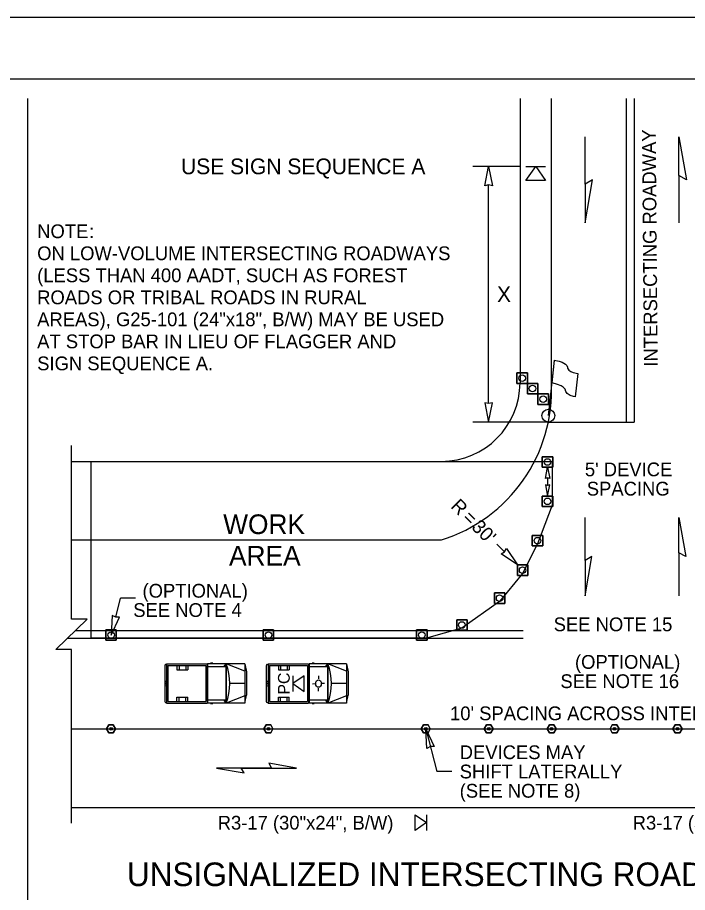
# Model space of a CAD drawing. Extents: x 99998.9 to 100095.7, y 99995 to 100010.7.
# Drawn here: x 100065.2 to 100068.607, y 100006.238 to 100010.687 of the extents above; entities that cross this region are included whole.
import ezdxf

# ---------------------------------------------------------------- set-up
doc = ezdxf.new("R2010")
doc.units = 0
for name, color, linetype in [('RD_ED_ShoulderPavedEdge', 7, 'Continuous'), ('RD_MK_LineDblYellowCenter', 7, 'Continuous'), ('RD_MK_LineEdgeWhite', 7, 'Continuous'), ('RD_MK_LineStop', 7, 'Continuous'), ('SH_DE_DetailBody1Text', 7, 'Continuous'), ('SH_DE_DetailHeading2Text', 7, 'Continuous'), ('SH_GI_PlotLimits', 7, 'Continuous'), ('SH_GI_SheetBorder', 7, 'Continuous'), ('TR_WZ_FlaggingStation', 7, 'Continuous'), ('TR_WZ_MotoristVehicle', 7, 'Continuous'), ('TR_WZ_PortableSignMountBlk-Org', 7, 'Continuous'), ('TR_WZ_PortableSignMountBlk-Wht', 7, 'Continuous'), ('TR_WZ_TrafficCone', 7, 'Continuous'), ('TR_WZ_TubularMarker', 7, 'Continuous'), ('TR_WZ_WorkAreaLabel', 7, 'Continuous'), ('TR_WZ_WorkZoneDetails', 7, 'Continuous'), ('TR_WZ_WorkZoneTextCurrent', 7, 'Continuous')]:
    doc.layers.add(name, color=color, linetype=linetype)

msp = doc.modelspace()

# ---------------------------------------------------------------- linework, layer by layer
at = {"layer": 'RD_ED_ShoulderPavedEdge'}
for p, q in [((100065.475, 100008.4304), (100067.355, 100008.4304)), ((100065.475, 100006.6704), (100070.275, 100006.6704))]:
    msp.add_line(p, q, dxfattribs=at)
msp.add_lwpolyline([(100067.755, 100010.275), (100067.755, 100008.8304)], dxfattribs=at)
msp.add_arc((100067.355, 100008.8304), 0.4, 270, 0, dxfattribs=at)
at = {"layer": 'RD_MK_LineDblYellowCenter'}
for p, q in [((100068.295, 100010.275), (100068.295, 100008.6304)), ((100068.335, 100010.275), (100068.335, 100008.6304)), ((100065.4957, 100007.5704), (100067.7712, 100007.5704)), ((100065.4543, 100007.5305), (100067.7712, 100007.5305))]:
    msp.add_line(p, q, dxfattribs=at)
at = {"layer": 'RD_MK_LineEdgeWhite'}
for p, q in [((100067.915, 100008.8304), (100067.915, 100010.275)), ((100065.475, 100008.0305), (100067.355, 100008.0305)), ((100065.475, 100007.0704), (100070.275, 100007.0704))]:
    msp.add_line(p, q, dxfattribs=at)
msp.add_arc((100067.1158, 100008.7939), 0.8, 287.3948, 2.6212, dxfattribs=at)
at = {"layer": 'RD_MK_LineStop'}
msp.add_line((100067.899, 100008.6304), (100068.335, 100008.6304), dxfattribs=at)
at = {"layer": 'SH_GI_PlotLimits'}
msp.add_lwpolyline([(100059.0625, 99999.6875), (100076.0625, 99999.6875), (100076.0625, 100010.6875), (100059.0625, 100010.6875)], close=True, dxfattribs=at)
at = {"layer": 'SH_GI_SheetBorder'}
msp.add_line((100060, 100010.375), (100075.75, 100010.375), dxfattribs=at)
at = {"layer": 'TR_WZ_FlaggingStation'}
for p, q in [((100067.899, 100008.6629), (100067.931, 100008.9439)), ((100067.918, 100008.8299), (100067.9311, 100008.9442)), ((100068.049, 100008.8764), (100068.0357, 100008.7592)), ((100067.918, 100008.8299), (100067.918, 100008.8299))]:
    msp.add_line(p, q, dxfattribs=at)
for points in [[(100067.9311, 100008.9442), (100067.9368, 100008.9429), (100067.9546, 100008.9395), (100067.9685, 100008.9353), (100067.9781, 100008.9292), (100067.9867, 100008.9245), (100067.9923, 100008.9177), (100067.9966, 100008.9098), (100067.9971, 100008.9037), (100068.0025, 100008.8944), (100068.0133, 100008.887), (100068.0257, 100008.8818), (100068.049, 100008.8764)], [(100068.0357, 100008.7592), (100068.0276, 100008.7606), (100068.0099, 100008.7653), (100067.9942, 100008.7758), (100067.9877, 100008.7863), (100067.9838, 100008.7966), (100067.9747, 100008.8075), (100067.9637, 100008.8137), (100067.9464, 100008.8208), (100067.918, 100008.8299)]]:
    msp.add_lwpolyline(points, dxfattribs=at)
msp.add_circle((100067.899, 100008.6629), 0.0325, dxfattribs=at)
at = {"layer": 'TR_WZ_MotoristVehicle'}
for p, q in [((100065.9487, 100007.3911), (100065.9487, 100007.2098)), ((100065.9532, 100007.3972), (100065.9577, 100007.3972)), ((100065.9577, 100007.3972), (100065.9577, 100007.2037)), ((100065.9584, 100007.4005), (100066.1641, 100007.4005)), ((100065.9584, 100007.4005), (100065.9584, 100007.2005)), ((100065.9642, 100007.3925), (100065.9642, 100007.2084)), ((100065.9642, 100007.3925), (100066.1582, 100007.3925)), ((100066.0106, 100007.3925), (100066.0106, 100007.3695)), ((100066.0106, 100007.3695), (100066.0655, 100007.3695)), ((100066.0215, 100007.3925), (100066.0215, 100007.3695)), ((100066.0556, 100007.3925), (100066.0556, 100007.3695)), ((100066.0655, 100007.3925), (100066.0655, 100007.3695)), ((100066.1582, 100007.3925), (100066.1582, 100007.2084)), ((100066.1641, 100007.4005), (100066.1641, 100007.2005)), ((100066.1668, 100007.4005), (100066.1668, 100007.2005)), ((100066.3557, 100007.4005), (100066.1668, 100007.4005)), ((100066.2596, 100007.385), (100066.1668, 100007.385)), ((100066.1926, 100007.4033), (100066.1813, 100007.4033)), ((100066.2596, 100007.4005), (100066.2475, 100007.385)), ((100066.2596, 100007.4005), (100066.2596, 100007.2005)), ((100066.2613, 100007.4005), (100066.2613, 100007.2005)), ((100066.3557, 100007.3638), (100066.2613, 100007.4005)), ((100066.3557, 100007.4005), (100066.3557, 100007.2005)), ((100066.3557, 100007.4005), (100066.365, 100007.3601)), ((100066.465, 100007.3911), (100066.465, 100007.2098)), ((100066.4695, 100007.3972), (100066.4739, 100007.3972)), ((100066.4739, 100007.3972), (100066.4739, 100007.2037)), ((100066.4746, 100007.4005), (100066.6803, 100007.4005)), ((100066.4746, 100007.4005), (100066.4746, 100007.2005)), ((100066.4805, 100007.3925), (100066.4805, 100007.2084)), ((100066.4805, 100007.3925), (100066.6745, 100007.3925)), ((100066.5268, 100007.3925), (100066.5268, 100007.3695)), ((100066.5268, 100007.3695), (100066.5818, 100007.3695)), ((100066.5378, 100007.3925), (100066.5378, 100007.3695)), ((100066.5718, 100007.3925), (100066.5718, 100007.3695)), ((100066.5818, 100007.3925), (100066.5818, 100007.3695)), ((100066.6745, 100007.3925), (100066.6745, 100007.2084)), ((100066.6803, 100007.4005), (100066.6803, 100007.2005)), ((100066.6831, 100007.4005), (100066.6831, 100007.2005)), ((100066.872, 100007.4005), (100066.6831, 100007.4005)), ((100066.7758, 100007.385), (100066.6831, 100007.385)), ((100066.7089, 100007.4033), (100066.6975, 100007.4033)), ((100066.7758, 100007.4005), (100066.7638, 100007.385)), ((100066.7758, 100007.4005), (100066.7758, 100007.2005)), ((100066.7775, 100007.4005), (100066.7775, 100007.2005)), ((100066.872, 100007.3638), (100066.7775, 100007.4005)), ((100066.872, 100007.4005), (100066.872, 100007.2005)), ((100066.872, 100007.4005), (100066.8813, 100007.3601)), ((100066.365, 100007.3601), (100066.365, 100007.2408)), ((100066.7305, 100007.3401), (100066.7305, 100007.3239)), ((100066.8813, 100007.3601), (100066.8813, 100007.2408)), ((100065.9487, 100007.3145), (100065.9577, 100007.3108)), ((100065.9487, 100007.2864), (100065.9577, 100007.2901)), ((100065.9511, 100007.3005), (100065.9553, 100007.3005)), ((100065.9532, 100007.3033), (100065.9532, 100007.2976)), ((100066.3557, 100007.3005), (100066.2798, 100007.3005)), ((100066.465, 100007.3145), (100066.4739, 100007.3108)), ((100066.465, 100007.2864), (100066.4739, 100007.2901)), ((100066.4674, 100007.3005), (100066.4715, 100007.3005)), ((100066.4695, 100007.3033), (100066.4695, 100007.2976)), ((100066.6996, 100007.2997), (100066.7145, 100007.3001)), ((100066.7164, 100007.3001), (100066.7164, 100007.3001)), ((100066.7298, 100007.262), (100066.7301, 100007.277)), ((100066.7606, 100007.3006), (100066.748, 100007.3005)), ((100066.872, 100007.3005), (100066.7961, 100007.3005)), ((100066.0106, 100007.2084), (100066.0106, 100007.2314)), ((100066.0106, 100007.2314), (100066.0655, 100007.2314)), ((100066.0215, 100007.2084), (100066.0215, 100007.2314)), ((100066.0556, 100007.2084), (100066.0556, 100007.2314)), ((100066.0655, 100007.2084), (100066.0655, 100007.2314)), ((100066.3557, 100007.2371), (100066.2613, 100007.2005)), ((100066.3557, 100007.2005), (100066.365, 100007.2408)), ((100066.5268, 100007.2084), (100066.5268, 100007.2314)), ((100066.5268, 100007.2314), (100066.5818, 100007.2314)), ((100066.5378, 100007.2084), (100066.5378, 100007.2314)), ((100066.5718, 100007.2084), (100066.5718, 100007.2314)), ((100066.5818, 100007.2084), (100066.5818, 100007.2314)), ((100066.872, 100007.2371), (100066.7775, 100007.2005)), ((100066.872, 100007.2005), (100066.8813, 100007.2408)), ((100065.9532, 100007.2037), (100065.9577, 100007.2037)), ((100065.9584, 100007.2005), (100066.1641, 100007.2005)), ((100065.9642, 100007.2084), (100066.1582, 100007.2084)), ((100066.2596, 100007.216), (100066.1668, 100007.216)), ((100066.3557, 100007.2005), (100066.1668, 100007.2005)), ((100066.1926, 100007.1976), (100066.1813, 100007.1976)), ((100066.2496, 100007.216), (100066.2596, 100007.2005)), ((100066.4695, 100007.2037), (100066.4739, 100007.2037)), ((100066.4746, 100007.2005), (100066.6803, 100007.2005)), ((100066.4805, 100007.2084), (100066.6745, 100007.2084)), ((100066.7758, 100007.216), (100066.6831, 100007.216)), ((100066.872, 100007.2005), (100066.6831, 100007.2005)), ((100066.7089, 100007.1976), (100066.6975, 100007.1976)), ((100066.7659, 100007.216), (100066.7758, 100007.2005))]:
    msp.add_line(p, q, dxfattribs=at)
for centre, major_axis, start_param, end_param in [((100065.9532, 100007.3911), (0, 0.0061), 6.283185, 7.853982), ((100066.1263, 100007.3004), (0, 0.2099), 4.215852, 5.209111), ((100066.4695, 100007.3911), (0, 0.0061), 6.283185, 7.853982), ((100066.6426, 100007.3004), (0, 0.2099), 4.215852, 5.209111), ((100065.9532, 100007.2098), (0, -0.0061), 4.712389, 6.283185), ((100066.4695, 100007.2098), (0, -0.0061), 4.712389, 6.283185)]:
    msp.add_ellipse(centre, major_axis=major_axis, ratio=0.73155, start_param=start_param, end_param=end_param, dxfattribs=at)
for centre, major_axis in [((100066.7305, 100007.3005), (0, -0.0193)), ((100065.9532, 100007.3005), (0, -0.00282)), ((100066.4695, 100007.3005), (0, -0.00282))]:
    msp.add_ellipse(centre, major_axis=major_axis, ratio=0.73155, dxfattribs=at)
at = {"layer": 'TR_WZ_PortableSignMountBlk-Org'}
msp.add_line((100067.785, 100009.9304), (100067.885, 100009.9304), dxfattribs=at)
msp.add_lwpolyline([(100067.8349, 100009.9304), (100067.885, 100009.8586), (100067.785, 100009.8586)], close=True, dxfattribs=at)
at = {"layer": 'TR_WZ_PortableSignMountBlk-Wht'}
for p, q in [((100066.6007, 100007.3404), (100066.6007, 100007.2604)), ((100067.279, 100006.6334), (100067.279, 100006.5534))]:
    msp.add_line(p, q, dxfattribs=at)
for points in [[(100066.6007, 100007.3004), (100066.6581, 100007.2604), (100066.6581, 100007.3404)], [(100067.279, 100006.5935), (100067.2215, 100006.5534), (100067.2215, 100006.6334)]]:
    msp.add_lwpolyline(points, close=True, dxfattribs=at)
at = {"layer": 'TR_WZ_TrafficCone'}
for points in [[(100067.7923, 100008.8803), (100067.7923, 100008.827), (100067.739, 100008.827), (100067.739, 100008.8803), (100067.7923, 100008.8803)], [(100067.739, 100008.8803), (100067.739, 100008.827), (100067.7923, 100008.827), (100067.7923, 100008.8803), (100067.739, 100008.8803)], [(100067.8456, 100008.827), (100067.8456, 100008.7736), (100067.7923, 100008.7736), (100067.7923, 100008.827), (100067.8456, 100008.827)], [(100067.7923, 100008.827), (100067.7923, 100008.7736), (100067.8456, 100008.7736), (100067.8456, 100008.827), (100067.7923, 100008.827)], [(100067.899, 100008.7736), (100067.899, 100008.7203), (100067.8456, 100008.7203), (100067.8456, 100008.7736), (100067.899, 100008.7736)], [(100067.8456, 100008.7736), (100067.8456, 100008.7203), (100067.899, 100008.7203), (100067.899, 100008.7736), (100067.8456, 100008.7736)], [(100067.8684, 100008.4538), (100067.9217, 100008.4538), (100067.9217, 100008.4005), (100067.8684, 100008.4005), (100067.8684, 100008.4538)], [(100067.8684, 100008.4005), (100067.9217, 100008.4005), (100067.9217, 100008.4538), (100067.8684, 100008.4538), (100067.8684, 100008.4005)], [(100067.8684, 100008.2538), (100067.9217, 100008.2538), (100067.9217, 100008.2005), (100067.8684, 100008.2005), (100067.8684, 100008.2538)], [(100067.8684, 100008.2005), (100067.9217, 100008.2005), (100067.9217, 100008.2538), (100067.8684, 100008.2538), (100067.8684, 100008.2005)], [(100067.8173, 100008.0538), (100067.8707, 100008.0538), (100067.8707, 100008.0005), (100067.8173, 100008.0005), (100067.8173, 100008.0538)], [(100067.8173, 100008.0005), (100067.8707, 100008.0005), (100067.8707, 100008.0538), (100067.8173, 100008.0538), (100067.8173, 100008.0005)], [(100067.7417, 100007.9038), (100067.795, 100007.9038), (100067.795, 100007.8505), (100067.7417, 100007.8505), (100067.7417, 100007.9038)], [(100067.7417, 100007.8505), (100067.795, 100007.8505), (100067.795, 100007.9038), (100067.7417, 100007.9038), (100067.7417, 100007.8505)], [(100067.6247, 100007.7615), (100067.6781, 100007.7615), (100067.6781, 100007.7082), (100067.6247, 100007.7082), (100067.6247, 100007.7615)], [(100067.6247, 100007.7082), (100067.6781, 100007.7082), (100067.6781, 100007.7615), (100067.6247, 100007.7615), (100067.6247, 100007.7082)], [(100067.433, 100007.6247), (100067.4864, 100007.6247), (100067.4864, 100007.5714), (100067.433, 100007.5714), (100067.433, 100007.6247)], [(100067.433, 100007.5714), (100067.4864, 100007.5714), (100067.4864, 100007.6247), (100067.433, 100007.6247), (100067.433, 100007.5714)], [(100065.649, 100007.5738), (100065.7024, 100007.5738), (100065.7024, 100007.5205), (100065.649, 100007.5205), (100065.649, 100007.5738)], [(100065.649, 100007.5205), (100065.7024, 100007.5205), (100065.7024, 100007.5738), (100065.649, 100007.5738), (100065.649, 100007.5205)], [(100066.449, 100007.5738), (100066.5024, 100007.5738), (100066.5024, 100007.5205), (100066.449, 100007.5205), (100066.449, 100007.5738)], [(100066.449, 100007.5205), (100066.5024, 100007.5205), (100066.5024, 100007.5738), (100066.449, 100007.5738), (100066.449, 100007.5205)], [(100067.229, 100007.5738), (100067.2824, 100007.5738), (100067.2824, 100007.5205), (100067.229, 100007.5205), (100067.229, 100007.5738)], [(100067.229, 100007.5205), (100067.2824, 100007.5205), (100067.2824, 100007.5738), (100067.229, 100007.5738), (100067.229, 100007.5205)]]:
    msp.add_lwpolyline(points, dxfattribs=at)
for centre in [(100067.7656, 100008.8536), (100067.819, 100008.8003), (100067.8723, 100008.747), (100067.895, 100008.4271), (100067.895, 100008.2271), (100067.844, 100008.0271), (100067.7683, 100007.8771), (100067.6514, 100007.7349), (100067.4597, 100007.598), (100065.6757, 100007.5471), (100066.4757, 100007.5471), (100067.2557, 100007.5471)]:
    msp.add_circle(centre, 0.0167, dxfattribs=at)
at = {"layer": 'TR_WZ_TubularMarker'}
for points in [[(100065.6526, 100007.0704), (100065.6641, 100007.0905), (100065.6872, 100007.0905), (100065.6988, 100007.0704), (100065.6872, 100007.0504), (100065.6641, 100007.0504)], [(100066.4526, 100007.0704), (100066.4641, 100007.0905), (100066.4872, 100007.0905), (100066.4988, 100007.0704), (100066.4872, 100007.0504), (100066.4641, 100007.0504)], [(100067.2526, 100007.0704), (100067.2641, 100007.0905), (100067.2872, 100007.0905), (100067.2988, 100007.0704), (100067.2872, 100007.0504), (100067.2641, 100007.0504)], [(100067.5726, 100007.0704), (100067.5841, 100007.0905), (100067.6072, 100007.0905), (100067.6188, 100007.0704), (100067.6072, 100007.0504), (100067.5841, 100007.0504)], [(100067.8926, 100007.0704), (100067.9041, 100007.0905), (100067.9272, 100007.0905), (100067.9388, 100007.0704), (100067.9272, 100007.0504), (100067.9041, 100007.0504)], [(100068.2126, 100007.0704), (100068.2241, 100007.0905), (100068.2472, 100007.0905), (100068.2588, 100007.0704), (100068.2472, 100007.0504), (100068.2241, 100007.0504)], [(100068.5326, 100007.0704), (100068.5441, 100007.0905), (100068.5672, 100007.0905), (100068.5788, 100007.0704), (100068.5672, 100007.0504), (100068.5441, 100007.0504)]]:
    msp.add_lwpolyline(points, close=True, dxfattribs=at)
for points in [[(100065.6641, 100007.0504), (100065.6872, 100007.0504), (100065.6988, 100007.0704), (100065.6872, 100007.0905), (100065.6641, 100007.0905), (100065.6526, 100007.0704), (100065.6641, 100007.0504)], [(100066.4641, 100007.0504), (100066.4872, 100007.0504), (100066.4988, 100007.0704), (100066.4872, 100007.0905), (100066.4641, 100007.0905), (100066.4526, 100007.0704), (100066.4641, 100007.0504)], [(100067.2641, 100007.0504), (100067.2872, 100007.0504), (100067.2988, 100007.0704), (100067.2872, 100007.0905), (100067.2641, 100007.0905), (100067.2526, 100007.0704), (100067.2641, 100007.0504)], [(100067.5841, 100007.0504), (100067.6072, 100007.0504), (100067.6188, 100007.0704), (100067.6072, 100007.0905), (100067.5841, 100007.0905), (100067.5726, 100007.0704), (100067.5841, 100007.0504)], [(100067.9041, 100007.0504), (100067.9272, 100007.0504), (100067.9388, 100007.0704), (100067.9272, 100007.0905), (100067.9041, 100007.0905), (100067.8926, 100007.0704), (100067.9041, 100007.0504)], [(100068.2241, 100007.0504), (100068.2472, 100007.0504), (100068.2588, 100007.0704), (100068.2472, 100007.0905), (100068.2241, 100007.0905), (100068.2126, 100007.0704), (100068.2241, 100007.0504)], [(100068.5441, 100007.0504), (100068.5672, 100007.0504), (100068.5788, 100007.0704), (100068.5672, 100007.0905), (100068.5441, 100007.0905), (100068.5326, 100007.0704), (100068.5441, 100007.0504)]]:
    msp.add_lwpolyline(points, dxfattribs=at)
for centre in [(100065.6757, 100007.0704), (100066.4757, 100007.0704), (100067.2757, 100007.0704), (100067.5957, 100007.0704), (100067.9157, 100007.0704), (100068.2357, 100007.0704), (100068.5557, 100007.0704)]:
    msp.add_circle(centre, 0.00667, dxfattribs=at)
at = {"layer": 'TR_WZ_WorkZoneDetails'}
for p, q in [((100065.25, 100010.275), (100065.25, 100001.6859)), ((100068.0855, 100009.8393), (100068.0855, 100010.0804)), ((100067.755, 100009.9304), (100067.515, 100009.9304)), ((100068.5627, 100009.8839), (100068.5627, 100009.6428)), ((100067.595, 100008.7242), (100067.595, 100009.8367)), ((100067.899, 100008.6304), (100067.515, 100008.6304)), ((100067.8951, 100008.3459), (100067.8951, 100008.3083)), ((100068.0855, 100007.9255), (100068.0855, 100008.1445)), ((100067.6754, 100007.9701), (100067.637, 100008.0085)), ((100068.5627, 100007.9659), (100068.5627, 100007.7469)), ((100065.6993, 100007.6378), (100065.7245, 100007.7352)), ((100065.8007, 100007.7352), (100065.7245, 100007.7352)), ((100067.2757, 100007.0704), (100067.3321, 100006.853)), ((100066.4922, 100006.8704), (100066.3378, 100006.8704)), ((100066.3378, 100006.8704), (100066.4922, 100006.8704)), ((100067.4083, 100006.853), (100067.3321, 100006.853))]:
    msp.add_line(p, q, dxfattribs=at)
for points in [[(100068.5627, 100010.0804), (100068.6013, 100009.8616), (100068.5627, 100009.8839)], [(100067.595, 100009.9304), (100067.6143, 100009.8322), (100067.595, 100009.8367), (100067.5757, 100009.8322)], [(100068.0855, 100009.6428), (100068.124, 100009.8616), (100068.0855, 100009.8393)], [(100067.595, 100008.6304), (100067.6143, 100008.7287), (100067.595, 100008.7242), (100067.5757, 100008.7287)], [(100067.9183, 100008.4304), (100067.9183, 100008.2071), (100067.844, 100008.0105), (100067.7683, 100007.8605), (100067.7683, 100007.8605), (100067.7683, 100007.8605), (100067.6514, 100007.7182), (100067.6514, 100007.7182), (100067.6514, 100007.7182), (100067.4597, 100007.5814), (100067.279, 100007.5305), (100066.499, 100007.5305), (100065.699, 100007.5305), (100065.575, 100007.5305), (100065.575, 100008.4304)], [(100067.895, 100008.4005), (100067.9063, 100008.3433), (100067.895, 100008.3459), (100067.8838, 100008.3433)], [(100067.8951, 100008.2538), (100067.9063, 100008.3109), (100067.8951, 100008.3083), (100067.8839, 100008.3109)], [(100068.5627, 100008.1445), (100068.5977, 100007.9457), (100068.5627, 100007.9659)], [(100067.7417, 100007.9038), (100067.6586, 100007.9597), (100067.6754, 100007.9701), (100067.6858, 100007.987)], [(100068.0855, 100007.7469), (100068.1205, 100007.9457), (100068.0855, 100007.9255)], [(100065.6757, 100007.5471), (100065.719, 100007.6374), (100065.6992, 100007.6379), (100065.6817, 100007.6471)], [(100067.2757, 100007.0704), (100067.319, 100006.9801), (100067.2992, 100006.9797), (100067.2816, 100006.9705)], [(100066.6179, 100006.8704), (100066.4779, 100006.8951), (100066.4922, 100006.8704)], [(100066.2121, 100006.8704), (100066.3521, 100006.8458), (100066.3378, 100006.8704)]]:
    msp.add_lwpolyline(points, close=True, dxfattribs=at)
msp.add_lwpolyline([(100065.475, 100006.5905), (100065.475, 100007.473), (100065.395, 100007.473), (100065.555, 100007.6279), (100065.475, 100007.6279), (100065.475, 100008.5105)], dxfattribs=at)

# ---------------------------------------------------------------- texts
at = {"layer": 'SH_DE_DetailBody1Text'}
msp.add_text('INTERSECTING ROADWAY', height=0.07, rotation=90.4626, dxfattribs=at).set_placement((100068.455, 100008.9122))
at = {"layer": 'SH_DE_DetailHeading2Text'}
msp.add_text('UNSIGNALIZED INTERSECTING ROADWAY DETAIL', height=0.12, rotation=360, dxfattribs=at).set_placement((100065.7563, 100006.2704))
at = {"layer": 'TR_WZ_MotoristVehicle'}
msp.add_text('PC', height=0.06, rotation=90, dxfattribs=at).set_placement((100066.5843, 100007.2444))
at = {"layer": 'TR_WZ_WorkAreaLabel'}
for s, p in [('WORK', (100066.2458, 100008.0605)), ('AREA', (100066.2754, 100007.9004))]:
    msp.add_text(s, height=0.1, dxfattribs=at).set_placement(p)
at = {"layer": 'TR_WZ_WorkZoneDetails'}
for s, p in [('NOTE', (100065.3, 100009.5654)), (':', (100065.5641, 100009.5654)), ('ON LOW-VOLUME INTERSECTING ROADWAYS ', (100065.3, 100009.4534)), ('(LESS THAN 400 AADT, SUCH AS FOREST ', (100065.3, 100009.3414)), ('ROADS OR TRIBAL ROADS IN RURAL ', (100065.3, 100009.2294)), ('AREAS), G25-101 (24"x18", B/W) MAY BE USED ', (100065.3, 100009.1174)), ('AT STOP BAR IN LIEU OF FLAGGER AND ', (100065.3, 100009.0054)), ('SIGN SEQUENCE A.', (100065.3, 100008.8934))]:
    msp.add_text(s, height=0.07, dxfattribs=at).set_placement(p)
for p in [(100066.2179, 100006.5576), (100068.3277, 100006.5575)]:
    msp.add_text('R3-17 (30"x24", B/W)', height=0.07, rotation=360, dxfattribs=at).set_placement(p)
at = {"layer": 'TR_WZ_WorkZoneTextCurrent'}
for s, height, p in [('USE SIGN SEQUENCE A', 0.08, (100066.0313, 100009.8904)), ('X', 0.08, (100067.6379, 100009.2404)), ("5' DEVICE", 0.07, (100068.0848, 100008.3544)), ('SPACING', 0.07, (100068.0944, 100008.2564)), ('(OPTIONAL)', 0.07, (100065.8355, 100007.7372)), ('SEE NOTE 4', 0.07, (100065.7886, 100007.6392)), ('SEE NOTE 15', 0.07, (100067.9261, 100007.5665)), ('(OPTIONAL)', 0.07, (100068.0344, 100007.3753)), ('SEE NOTE 16', 0.07, (100067.9603, 100007.2773)), ("10' SPACING ACROSS INTERSECTION", 0.07, (100067.3993, 100007.1138)), ('DEVICES MAY', 0.07, (100067.4483, 100006.916)), ('SHIFT LATERALLY', 0.07, (100067.4483, 100006.818)), ('(SEE NOTE 8)', 0.07, (100067.4483, 100006.72))]:
    msp.add_text(s, height=height, dxfattribs=at).set_placement(p)
for s, p in [('R', (100067.3982, 100008.1977)), ('=', (100067.4574, 100008.1386)), ("30'", (100067.5042, 100008.0917))]:
    msp.add_text(s, height=0.07, rotation=315, dxfattribs=at).set_placement(p)

doc.saveas('drawing.dxf')
